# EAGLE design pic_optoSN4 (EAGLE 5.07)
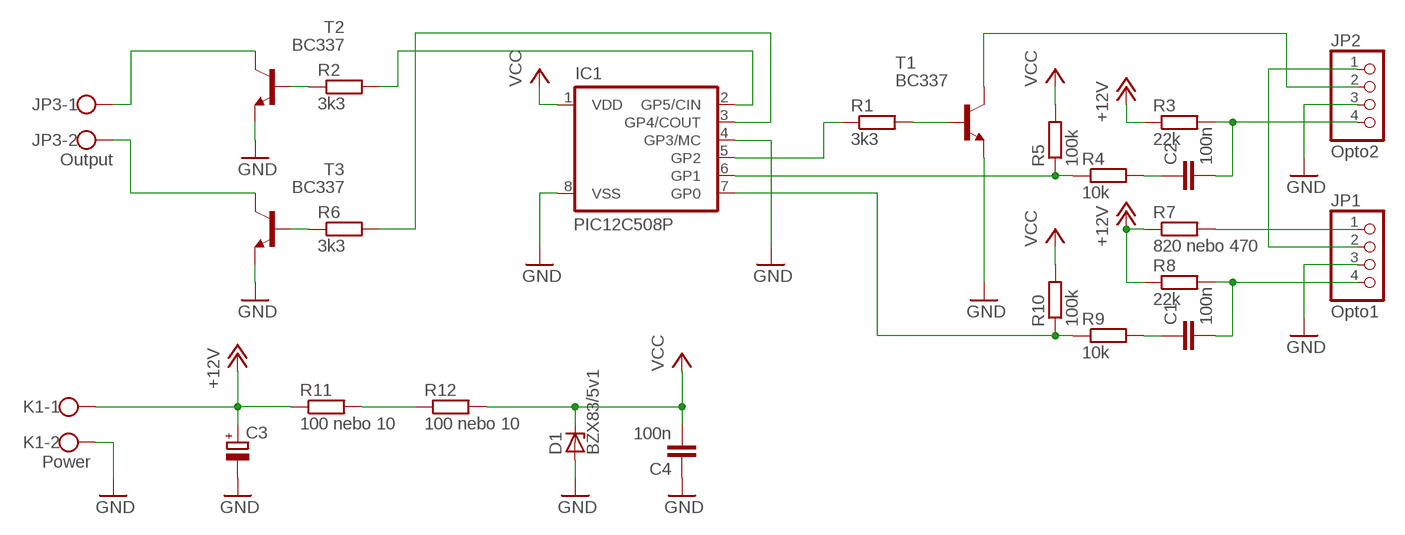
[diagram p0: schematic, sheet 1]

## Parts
C1  100n  C-EU050-025X075  [C050-025X075]
C2  100n  C-EU050-025X075  [C050-025X075]
C3  CPOL-EUE2-5  [E2-5]
C4  100n  C-EU050-025X075  [C050-025X075]
D1  BZX83/5v1  ZENER-DIODEDO35Z10  [DO35Z10]
IC1  PIC12C508P  [DIL8]
JP1  Opto1  PINHD-1X4/90  [1X04/90]
JP2  Opto2  PINHD-1X4/90  [1X04/90]
JP3  Output  W237-02P  [W237-132]
K1  Power  W237-02P  [W237-132]
R1  3k3  R-EU_0207/10  [0207/10]
R2  3k3  R-EU_0207/10  [0207/10]
R3  22k  R-EU_0207/10  [0207/10]
R4  10k  R-EU_0207/10  [0207/10]
R5  100k  R-EU_0207/10  [0207/10]
R6  3k3  R-EU_0207/10  [0207/10]
R7  820 nebo 470  R-EU_0207/10  [0207/10]
R8  22k  R-EU_0207/10  [0207/10]
R9  10k  R-EU_0207/10  [0207/10]
R10  100k  R-EU_0207/10  [0207/10]
R11  100 nebo 10  R-EU_0207/10  [0207/10]
R12  100 nebo 10  R-EU_0207/10  [0207/10]
T1  BC337  BC337-16-NPN-TO92-EBC  [TO92-EBC]
T2  BC337  BC337-16-NPN-TO92-EBC  [TO92-EBC]
T3  BC337  BC337-16-NPN-TO92-EBC  [TO92-EBC]

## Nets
+12V: C3.+ K1.1 R3.1 R7.1 R8.1 R11.1
GND: C3.- C4.1 D1.A IC1.4(GP3/MC) IC1.8(VSS) JP1.3 JP2.3 K1.2 T1.E T2.E T3.E
N$1: JP3.2 T3.C
N$2: JP3.1 T2.C
N$3: IC1.2(GP5/CIN) R2.2
N$4: R2.1 T2.B
N$5: IC1.3(GP4/COUT) R6.2
N$6: R6.1 T3.B
N$7: IC1.5(GP2) R1.1
N$8: R1.2 T1.B
N$9: JP2.2 T1.C
N$10: IC1.6(GP1) R4.1 R5.1
N$11: C2.1 R4.2
N$12: C2.2 JP2.4 R3.2
N$13: IC1.7(GP0) R9.1 R10.1
N$14: C1.1 R9.2
N$15: C1.2 JP1.4 R8.2
N$16: JP1.1 R7.2
N$17: JP1.2 JP2.1
N$19: R11.2 R12.1
VCC: C4.2 D1.C IC1.1(VDD) R5.2 R10.2 R12.2

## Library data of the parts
C1 C2 C4 = rcl:C-EU: CAPACITOR, European symbol
C3 = rcl:CPOL-EU: POLARIZED CAPACITOR, European symbol
D1 = diode:ZENER-DIODE: Z-Diode
IC1 = microchip:PIC12C*?: MICROCONTROLLER
JP1 JP2 = pinhead:PINHD-1X4: PIN HEADER
JP3 K1 = con-wago-508:W237-02P: WAGO SREW CLAMP
R1-R12 = rcl:R-EU_: RESISTOR, European symbol
T1-T3 = transistor:*-NPN-: NPN Transistror BF959 corrected 2008.03.06

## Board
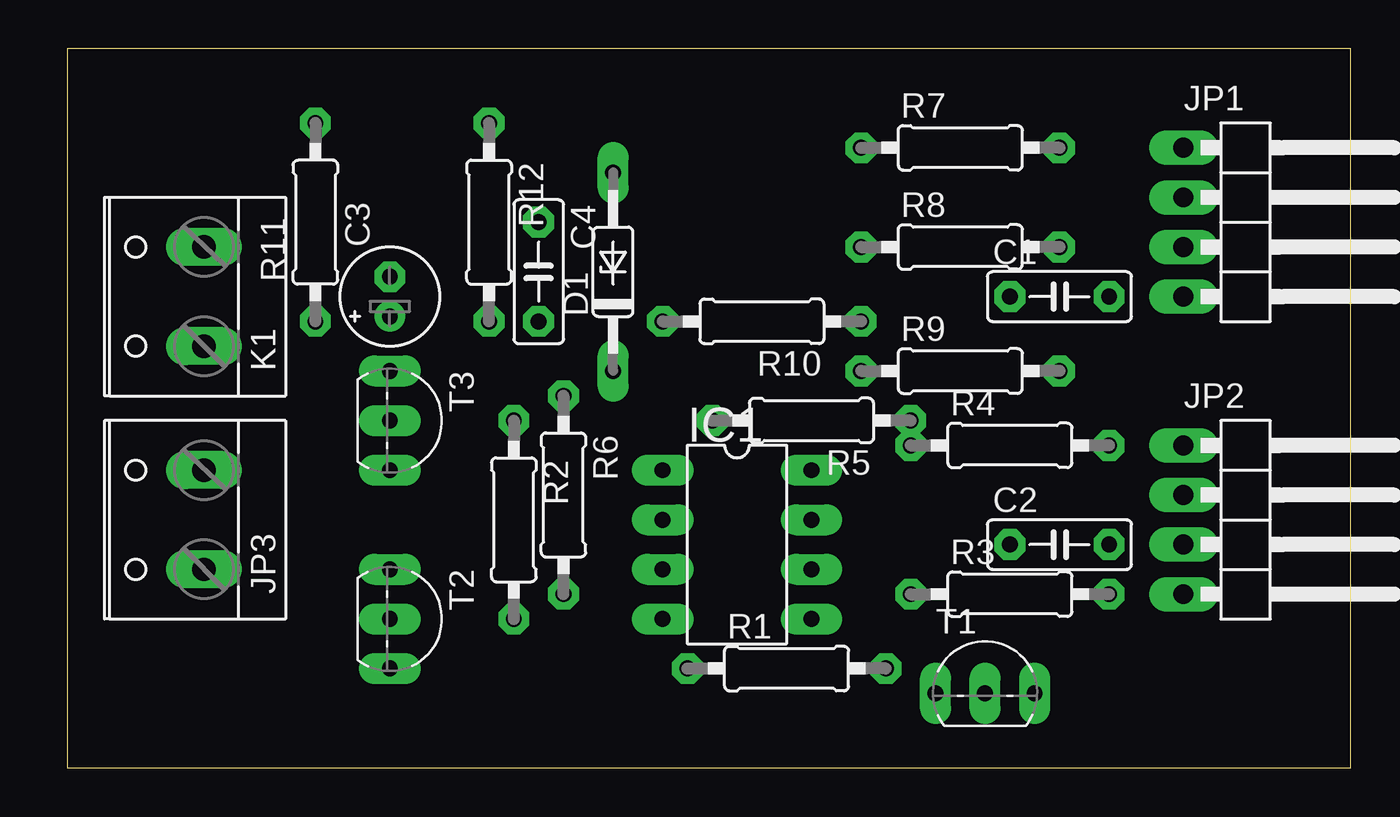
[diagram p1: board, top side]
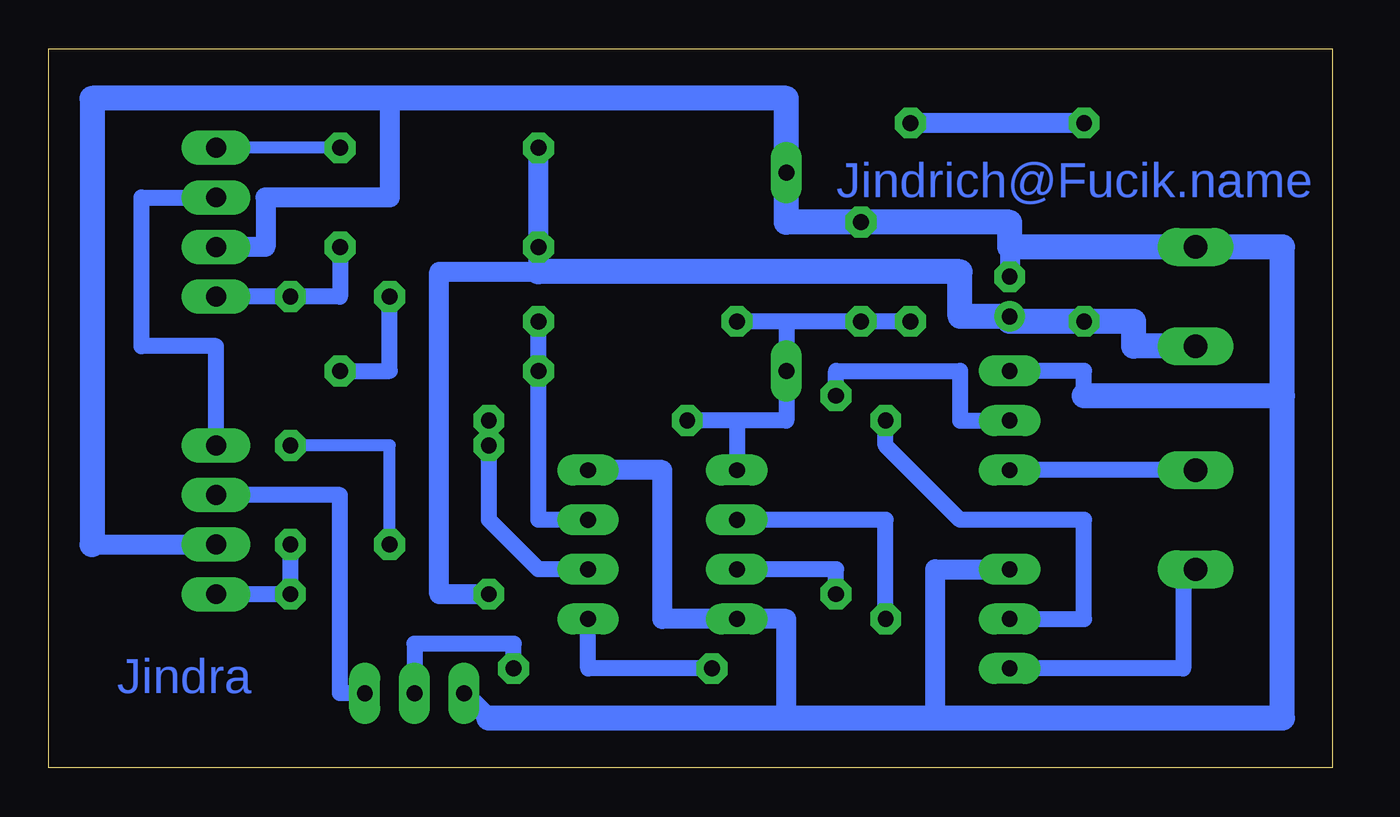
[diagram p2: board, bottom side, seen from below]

Size 65.71 x 36.82 mm. Coordinates in mm from the lower left corner, seen from the top.
Outline: 0,0 65.71,0 65.71,36.82 0,36.82 0,0
Copper layers (1*16): Top 0.035mm / dielectric 1.5mm / Bottom 0.035mm
Design rules "default *": minimum track width 10mil, minimum drill 24mil, track to track 8mil, track to pad 8mil, pad to pad 8mil, via to via 8mil, smd to smd 8mil, copper to edge 40mil, drill to drill 8mil, minimum pad ring 15mil, minimum via ring 8mil, stop-mask expansion 4mil, vias tented up to drill 0mil, thermal gap 10mil

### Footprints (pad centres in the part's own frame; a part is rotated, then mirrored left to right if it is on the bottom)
C050-025X075 = drill 0.813 octagon: 1 -2.54,0; 2 2.54,0
E2-5 = drill 0.813 pad 1.27 round: + -1.016,0 | drill 0.813 pad 1.27 octagon: - 1.016,0
DO35Z10 = drill 0.813 long: A 5.08,0; C -5.08,0
DIL8 = drill 0.813 long: 1 -3.81,-3.81; 2 -1.27,-3.81; 3 1.27,-3.81; 4 3.81,-3.81; 5 3.81,3.81; 6 1.27,3.81; 7 -1.27,3.81; 8 -3.81,3.81
1X04/90 = drill 1.016 long: 1 -3.81,-3.81; 2 -1.27,-3.81; 3 1.27,-3.81; 4 3.81,-3.81
W237-132 = drill 1.194 long: 1 -2.54,-0.635; 2 2.54,-0.635
0207/10 = drill 0.813 octagon: 1 -5.08,0; 2 5.08,0
TO92-EBC = drill 0.813 long: B 0,-1.27; C 2.54,-1.27; E -2.54,-1.27

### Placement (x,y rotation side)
C1  50.8,24.13 0 top
C2  50.8,11.43 0 top
C3  16.51,24.13 90 top
C4  24.13,25.4 270 top
D1  27.94,25.4 90 top
IC1  34.29,11.43 270 top
JP1  60.96,27.94 270 top
JP2  60.96,12.7 270 top
JP3  6.35,12.7 90 top
K1  6.35,24.13 90 top
R1  36.83,5.08 0 top
R2  22.86,12.7 270 top
R3  48.26,8.89 0 top
R4  48.26,16.51 0 top
R5  38.1,17.78 180 top
R6  25.4,13.97 270 top
R7  45.72,31.75 0 top
R8  45.72,26.67 0 top
R9  45.72,20.32 0 top
R10  35.56,22.86 180 top
R11  12.7,27.94 90 top
R12  21.59,27.94 270 top
T1  46.99,5.08 0 top
T2  17.78,7.62 270 top
T3  17.78,17.78 270 top

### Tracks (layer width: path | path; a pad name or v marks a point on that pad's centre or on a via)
+12V
  Bottom 1.016: R7.1 R8.1 40.64,25.4 45.72,25.4 45.72,8.89 R3.1 | 16.51,22.86 C3.+
  Bottom 1.27: 40.64,25.4 19.05,25.4 19.05,23.11 C3.+ | K1.1 10.16,21.59 10.16,22.86 R11.1 16.51,22.86
GND
  Bottom 0.813: T3.E 12.7,20.32 12.7,19.05
  Bottom 1.016: 16.51,26.67 C3.- | 43.18,2.54 T1.E | 63.5,11.43 JP2.3 | JP1.3 54.61,26.67 54.61,29.21 48.26,29.21 48.26,34.29 | T2.E 20.32,10.16 20.32,2.54 | 27.94,2.54 27.94,7.62 IC1.4 34.29,7.62 34.29,15.24 IC1.8
  Bottom 1.27: 43.18,2.54 27.94,2.54 20.32,2.54 2.54,2.54 2.54,19.05 | 63.5,11.43 63.5,34.29 48.26,34.29 27.94,34.29 D1.A 27.94,27.94 C4.1 16.51,27.94 16.51,26.67 K1.2 2.54,26.67 2.54,19.05 | 2.54,19.05 12.7,19.05
N$1
  Bottom 0.813: JP3.2 T3.C
N$2
  Bottom 0.254: JP3.1 7.62,10.16
  Bottom 0.813: T2.C 7.62,5.08 7.62,10.16
N$3
  Bottom 0.813: R2.2 22.86,12.7 IC1.2
N$4
  Bottom 0.813: T2.B 12.7,7.62 12.7,12.7 19.05,12.7 22.86,16.51 R2.1
N$5
  Bottom 0.813: R6.2 25.4,10.16 IC1.3
N$6
  Bottom 0.813: R6.1 25.4,20.32 19.05,20.32 19.05,17.78 T3.B
N$7
  Bottom 0.813: R1.1 38.1,5.08 IC1.5
N$8
  Bottom 0.813: R1.2 41.91,6.35 46.99,6.35 T1.B
N$9
  Bottom 0.813: T1.C 50.8,3.81 50.8,13.97 JP2.2
N$10
  Bottom 0.813: IC1.6 40.64,10.16 43.18,12.7 R4.1 R5.1
N$11
  Bottom 0.61: C2.1 48.26,16.51 R4.2
N$12
  Bottom 0.813: C2.2 R3.2 JP2.4
N$13
  Bottom 0.813: IC1.7 40.64,12.7 R9.1 R10.1
N$14
  Bottom 0.813: R9.2 48.26,20.32 C1.1
N$15
  Bottom 0.813: JP1.4 C1.2 50.8,24.13 R8.2
N$16
  Bottom 0.61: R7.2 JP1.1
N$17
  Bottom 0.813: JP2.1 57.15,21.59 60.96,21.59 60.96,29.21 JP1.2
N$19
  Bottom 1.016: R11.2 R12.1
VCC
  Bottom 0.813: R12.2 C4.2 27.94,22.86 | 27.94,22.86 D1.C 27.94,17.78 30.48,17.78 | 27.94,22.86 R10.2 | 30.48,17.78 R5.2 | 30.48,17.78 IC1.1

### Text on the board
Bottom: Jindrich@Fucik.name | Jindra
